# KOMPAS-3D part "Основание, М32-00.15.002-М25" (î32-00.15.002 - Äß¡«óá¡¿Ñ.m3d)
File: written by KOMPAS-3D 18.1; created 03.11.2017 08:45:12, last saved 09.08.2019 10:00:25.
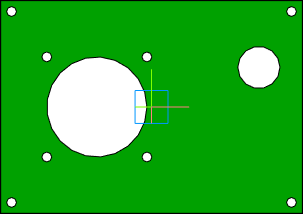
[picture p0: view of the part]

Document properties: Автор: Милов; Организация: Милов; Полное имя файла: D:\Magna\Магна Ins\Магна ins 32\М32-00.15.002 - Основание.m3d

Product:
- Part/product: Основание  | designation М32-00.15.002-М25
    Материал: Полипропилен  ГОСТ 26996-86 (density 900 kg/m3)
    Масса: 1.82071
    Раздел спецификации: Детали
    Форматы листов документа: A3
- Part/product: Основание  | designation М32-00.15.002
    Материал: Полипропилен  ГОСТ 26996-86 (density 900 kg/m3)
    Масса: 2.27958
    Раздел спецификации: Детали
    Форматы листов документа: A3
    source file: М32-00.15.002 - Основание.cdw, М32-00.15.002-М25 - Основание.cdw
- Part/product: Основание  | designation М32-10.15.002-ПВХ
    Материал: Полипропилен  ГОСТ 26996-86 (density 900 kg/m3)
    Масса: 2.27958
    Раздел спецификации: Детали
    Форматы листов документа: A3

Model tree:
1. Эскиз:1
2. Операция выдавливания:1
     Расстояние 1 = 20
3. Отверстие:1
     Глубина выреза = 20; Диаметр отверстия = 15; Угол конуса торца = 118; Координата X = -159.014; Координата Y = 76.014
4. Массив по концентрической сетке:1  (with: Отверстие:1, Эскиз:1)  (4 pattern instances)
     Шаг 2 = 360
5. Фаска:1
     Угол = 45; Длина 1 = 1; Длина 2 = 1
6. Эскиз:2
7. Вырезать элемент выдавливания:1
8. Массив по сетке:1  (with: Вырезать элемент выдавливания:1, Эскиз:2)  (labels: Полипропилен  ГОСТ 26996-86)  (4 pattern instances)
     Угол раствора = 90

Expressions: v454*2; v455*2; 137+5+3; 270/2; 360/2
